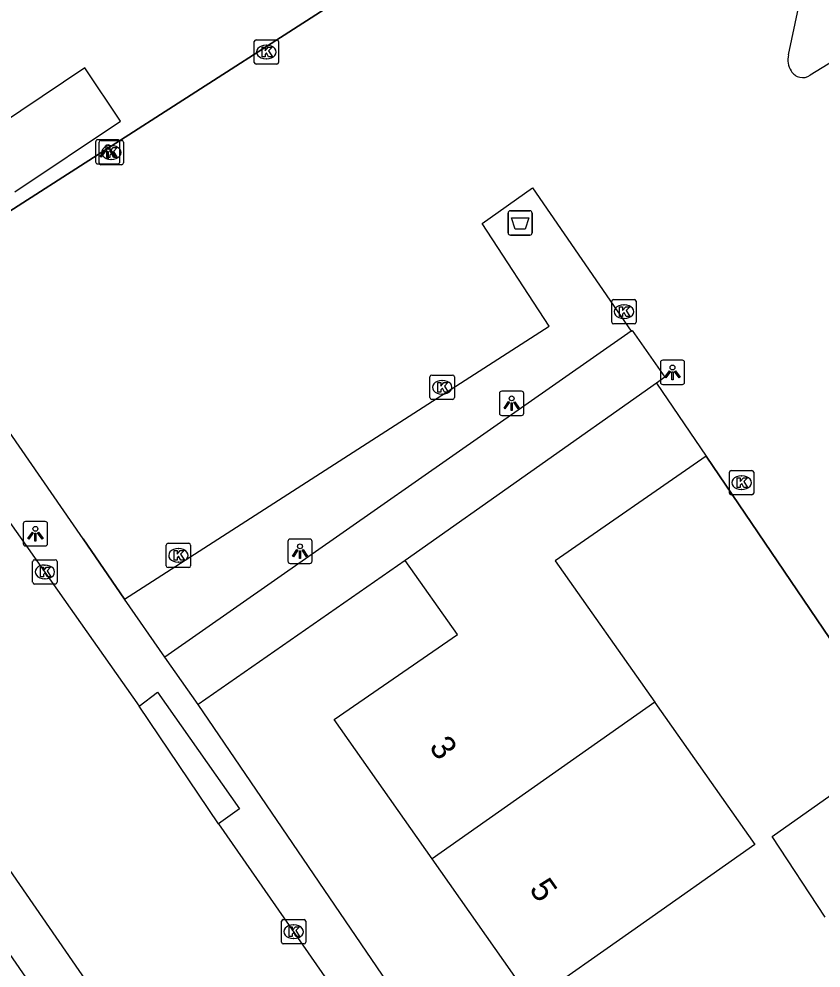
# Model space of a CAD drawing. Extents: x 161845 to 162341, y 381620 to 382158.
# Drawn here: x 162009.89 to 162042.81, y 381891.32 to 381930.27 of the extents above; entities that cross this region are included whole.
import ezdxf

# ---------------------------------------------------------------- set-up
doc = ezdxf.new("R2010")
doc.units = 0
for name, color, linetype in [('IMGEO_Afvalbak', 7, 'Continuous'), ('IMGEO_Kolk', 7, 'Continuous'), ('IMGEO_Lichtpunt', 7, 'Continuous'), ('IMGEO_Muur', 7, 'Continuous'), ('IMGEO_Pand', 7, 'Continuous'), ('IMGEO_Pand_nummerreeks', 7, 'Continuous'), ('IMGEO_Parkeervlak_gesloten', 7, 'Continuous'), ('IMGEO_Rijbaan_lokaal_open', 7, 'Continuous'), ('IMGEO_Voetpad_open', 7, 'Continuous')]:
    doc.layers.add(name, color=color, linetype=linetype)

msp = doc.modelspace()

# ---------------------------------------------------------------- linework, layer by layer
at = {"layer": 'IMGEO_Afvalbak'}
for p, q in [((162029.967, 381921.5), (162029.967, 381922.3)), ((162029.967, 381922.3), (162029.967, 381921.5)), ((162030.067, 381922.4), (162030.857, 381922.4)), ((162030.857, 381922.4), (162030.067, 381922.4)), ((162030.957, 381922.3), (162030.957, 381921.5)), ((162030.957, 381921.5), (162030.957, 381922.3)), ((162030.857, 381921.4), (162030.067, 381921.4)), ((162030.067, 381921.4), (162030.857, 381921.4))]:
    msp.add_line(p, q, dxfattribs=at)
msp.add_lwpolyline([(162030.11, 381922.114), (162030.814, 381922.114), (162030.665, 381921.644), (162030.259, 381921.644), (162030.11, 381922.114)], dxfattribs=at)
for centre, start, end in [((162030.067, 381922.3), 90, 180), ((162030.067, 381922.3), 90, 180), ((162030.857, 381922.3), 0, 90), ((162030.857, 381922.3), 360, 90), ((162030.067, 381921.5), 180, 270), ((162030.067, 381921.5), 180, 270), ((162030.857, 381921.5), 270, 0), ((162030.857, 381921.5), 270, 0)]:
    msp.add_arc(centre, 0.1, start, end, dxfattribs=at)
at = {"layer": 'IMGEO_Kolk'}
for p, q in [((162019.547, 381928.492), (162019.547, 381929.344)), ((162019.622, 381929.418), (162020.474, 381929.418)), ((162020.548, 381929.344), (162020.548, 381928.492)), ((162020.035, 381929.198), (162020.06, 381929.198)), ((162020.058, 381928.638), (162020.033, 381928.638)), ((162020.474, 381928.418), (162019.622, 381928.418)), ((162013.18, 381924.365), (162013.18, 381925.217)), ((162013.255, 381925.291), (162014.107, 381925.291)), ((162013.668, 381925.071), (162013.693, 381925.071)), ((162014.181, 381925.217), (162014.181, 381924.365)), ((162014.107, 381924.291), (162013.255, 381924.291)), ((162013.691, 381924.511), (162013.666, 381924.511)), ((162034.224, 381917.833), (162034.224, 381918.685)), ((162034.299, 381918.759), (162035.151, 381918.759)), ((162034.712, 381918.539), (162034.737, 381918.539)), ((162035.225, 381918.685), (162035.225, 381917.833)), ((162035.151, 381917.759), (162034.299, 381917.759)), ((162034.735, 381917.979), (162034.71, 381917.979)), ((162026.762, 381914.731), (162026.762, 381915.583)), ((162026.837, 381915.657), (162027.689, 381915.657)), ((162027.25, 381915.437), (162027.275, 381915.437)), ((162027.763, 381915.583), (162027.763, 381914.731)), ((162027.689, 381914.657), (162026.837, 381914.657)), ((162027.273, 381914.877), (162027.248, 381914.877)), ((162039.053, 381910.815), (162039.053, 381911.667)), ((162039.128, 381911.741), (162039.98, 381911.741)), ((162039.541, 381911.521), (162039.566, 381911.521)), ((162040.054, 381911.667), (162040.054, 381910.815)), ((162039.98, 381910.741), (162039.128, 381910.741)), ((162039.564, 381910.961), (162039.539, 381910.961)), ((162015.937, 381907.831), (162015.937, 381908.683)), ((162016.012, 381908.757), (162016.864, 381908.757)), ((162016.938, 381908.683), (162016.938, 381907.831)), ((162016.425, 381908.537), (162016.45, 381908.537)), ((162010.454, 381907.153), (162010.454, 381908.005)), ((162010.529, 381908.079), (162011.381, 381908.079)), ((162011.455, 381908.005), (162011.455, 381907.153)), ((162016.448, 381907.977), (162016.423, 381907.977)), ((162010.942, 381907.859), (162010.967, 381907.859)), ((162016.864, 381907.757), (162016.012, 381907.757)), ((162010.965, 381907.299), (162010.94, 381907.299)), ((162011.381, 381907.079), (162010.529, 381907.079)), ((162020.667, 381892.386), (162020.667, 381893.238)), ((162020.742, 381893.312), (162021.594, 381893.312)), ((162021.155, 381893.092), (162021.18, 381893.092)), ((162021.668, 381893.238), (162021.668, 381892.386)), ((162021.594, 381892.312), (162020.742, 381892.312)), ((162021.178, 381892.532), (162021.153, 381892.532))]:
    msp.add_line(p, q, dxfattribs=at)
for points in [[(162019.547, 381928.492), (162019.547, 381929.344)], [(162019.622, 381929.418), (162020.474, 381929.418)], [(162020.548, 381929.344), (162020.548, 381928.492)], [(162019.868, 381929.118), (162019.991, 381929.118), (162019.991, 381928.967), (162020.121, 381929.118), (162020.285, 381929.118), (162020.139, 381928.967), (162020.292, 381928.718), (162020.14, 381928.718), (162020.055, 381928.882), (162019.991, 381928.815), (162019.991, 381928.718), (162019.868, 381928.718), (162019.868, 381929.118)], [(162020.474, 381928.418), (162019.622, 381928.418)], [(162013.18, 381924.365), (162013.18, 381925.217)], [(162013.255, 381925.291), (162014.107, 381925.291)], [(162014.181, 381925.217), (162014.181, 381924.365)], [(162013.501, 381924.991), (162013.624, 381924.991), (162013.624, 381924.84), (162013.754, 381924.991), (162013.918, 381924.991), (162013.772, 381924.84), (162013.925, 381924.591), (162013.773, 381924.591), (162013.688, 381924.755), (162013.624, 381924.688), (162013.624, 381924.591), (162013.501, 381924.591), (162013.501, 381924.991)], [(162014.107, 381924.291), (162013.255, 381924.291)], [(162034.224, 381917.833), (162034.224, 381918.685)], [(162034.299, 381918.759), (162035.151, 381918.759)], [(162034.545, 381918.459), (162034.668, 381918.459), (162034.668, 381918.308), (162034.798, 381918.459), (162034.962, 381918.459), (162034.816, 381918.308), (162034.969, 381918.059), (162034.817, 381918.059), (162034.732, 381918.223), (162034.668, 381918.156), (162034.668, 381918.059), (162034.545, 381918.059), (162034.545, 381918.459)], [(162035.225, 381918.685), (162035.225, 381917.833)], [(162035.151, 381917.759), (162034.299, 381917.759)], [(162026.762, 381914.731), (162026.762, 381915.583)], [(162026.837, 381915.657), (162027.689, 381915.657)], [(162027.083, 381915.357), (162027.206, 381915.357), (162027.206, 381915.206), (162027.336, 381915.357), (162027.5, 381915.357), (162027.354, 381915.206), (162027.507, 381914.957), (162027.355, 381914.957), (162027.27, 381915.121), (162027.206, 381915.054), (162027.206, 381914.957), (162027.083, 381914.957), (162027.083, 381915.357)], [(162027.763, 381915.583), (162027.763, 381914.731)], [(162027.689, 381914.657), (162026.837, 381914.657)], [(162039.053, 381910.815), (162039.053, 381911.667)], [(162039.128, 381911.741), (162039.98, 381911.741)], [(162039.374, 381911.441), (162039.497, 381911.441), (162039.497, 381911.29), (162039.627, 381911.441), (162039.791, 381911.441), (162039.645, 381911.29), (162039.798, 381911.041), (162039.646, 381911.041), (162039.561, 381911.205), (162039.497, 381911.138), (162039.497, 381911.041), (162039.374, 381911.041), (162039.374, 381911.441)], [(162040.054, 381911.667), (162040.054, 381910.815)], [(162039.98, 381910.741), (162039.128, 381910.741)], [(162015.937, 381907.831), (162015.937, 381908.683)], [(162016.012, 381908.757), (162016.864, 381908.757)], [(162016.938, 381908.683), (162016.938, 381907.831)], [(162016.258, 381908.457), (162016.381, 381908.457), (162016.381, 381908.306), (162016.511, 381908.457), (162016.675, 381908.457), (162016.529, 381908.306), (162016.682, 381908.057), (162016.53, 381908.057), (162016.445, 381908.221), (162016.381, 381908.154), (162016.381, 381908.057), (162016.258, 381908.057), (162016.258, 381908.457)], [(162010.454, 381907.153), (162010.454, 381908.005)], [(162010.529, 381908.079), (162011.381, 381908.079)], [(162011.455, 381908.005), (162011.455, 381907.153)], [(162010.775, 381907.779), (162010.898, 381907.779), (162010.898, 381907.628), (162011.028, 381907.779), (162011.192, 381907.779), (162011.046, 381907.628), (162011.199, 381907.379), (162011.047, 381907.379), (162010.962, 381907.543), (162010.898, 381907.476), (162010.898, 381907.379), (162010.775, 381907.379), (162010.775, 381907.779)], [(162016.864, 381907.757), (162016.012, 381907.757)], [(162011.381, 381907.079), (162010.529, 381907.079)], [(162020.667, 381892.386), (162020.667, 381893.238)], [(162020.742, 381893.312), (162021.594, 381893.312)], [(162021.668, 381893.238), (162021.668, 381892.386)], [(162020.988, 381893.012), (162021.111, 381893.012), (162021.111, 381892.861), (162021.241, 381893.012), (162021.405, 381893.012), (162021.259, 381892.861), (162021.412, 381892.612), (162021.26, 381892.612), (162021.175, 381892.776), (162021.111, 381892.709), (162021.111, 381892.612), (162020.988, 381892.612), (162020.988, 381893.012)], [(162021.594, 381892.312), (162020.742, 381892.312)]]:
    msp.add_lwpolyline(points, dxfattribs=at)
for centre, start, end in [((162019.624, 381929.342), 91.552, 178.448), ((162019.624, 381929.342), 91.552, 178.448), ((162020.472, 381929.342), 1.552, 88.448), ((162020.472, 381929.342), 1.552, 88.448), ((162019.624, 381928.494), 181.552, 268.448), ((162019.624, 381928.494), 181.552, 268.448), ((162020.472, 381928.494), 271.552, 358.448), ((162020.472, 381928.494), 271.552, 358.448), ((162013.257, 381925.215), 91.552, 178.448), ((162013.257, 381925.215), 91.552, 178.448), ((162014.105, 381925.215), 1.552, 88.448), ((162014.105, 381925.215), 1.552, 88.448), ((162013.257, 381924.367), 181.552, 268.448), ((162013.257, 381924.367), 181.552, 268.448), ((162014.105, 381924.367), 271.552, 358.448), ((162014.105, 381924.367), 271.552, 358.448), ((162034.301, 381918.683), 91.552, 178.448), ((162034.301, 381918.683), 91.552, 178.448), ((162035.149, 381918.683), 1.552, 88.448), ((162035.149, 381918.683), 1.552, 88.448), ((162034.301, 381917.835), 181.552, 268.448), ((162034.301, 381917.835), 181.552, 268.448), ((162035.149, 381917.835), 271.552, 358.448), ((162035.149, 381917.835), 271.552, 358.448), ((162026.839, 381915.581), 91.552, 178.448), ((162026.839, 381915.581), 91.552, 178.448), ((162027.687, 381915.581), 1.552, 88.448), ((162027.687, 381915.581), 1.552, 88.448), ((162026.839, 381914.733), 181.552, 268.448), ((162026.839, 381914.733), 181.552, 268.448), ((162027.687, 381914.733), 271.552, 358.448), ((162027.687, 381914.733), 271.552, 358.448), ((162039.13, 381911.665), 91.552, 178.448), ((162039.13, 381911.665), 91.552, 178.448), ((162039.978, 381911.665), 1.552, 88.448), ((162039.978, 381911.665), 1.552, 88.448), ((162039.13, 381910.817), 181.552, 268.448), ((162039.13, 381910.817), 181.552, 268.448), ((162039.978, 381910.817), 271.552, 358.448), ((162039.978, 381910.817), 271.552, 358.448), ((162016.014, 381908.681), 91.552, 178.448), ((162016.014, 381908.681), 91.552, 178.448), ((162016.862, 381908.681), 1.552, 88.448), ((162016.862, 381908.681), 1.552, 88.448), ((162010.531, 381908.003), 91.552, 178.448), ((162010.531, 381908.003), 91.552, 178.448), ((162011.379, 381908.003), 1.552, 88.448), ((162011.379, 381908.003), 1.552, 88.448), ((162016.014, 381907.833), 181.552, 268.448), ((162016.014, 381907.833), 181.552, 268.448), ((162016.862, 381907.833), 271.552, 358.448), ((162016.862, 381907.833), 271.552, 358.448), ((162010.531, 381907.155), 181.552, 268.448), ((162010.531, 381907.155), 181.552, 268.448), ((162011.379, 381907.155), 271.552, 358.448), ((162011.379, 381907.155), 271.552, 358.448), ((162020.744, 381893.236), 91.552, 178.448), ((162020.744, 381893.236), 91.552, 178.448), ((162021.592, 381893.236), 1.552, 88.448), ((162021.592, 381893.236), 1.552, 88.448), ((162020.744, 381892.388), 181.552, 268.448), ((162020.744, 381892.388), 181.552, 268.448), ((162021.592, 381892.388), 271.552, 358.448), ((162021.592, 381892.388), 271.552, 358.448)]:
    msp.add_arc(centre, 0.0765, start, end, dxfattribs=at)
for centre, major_axis, ratio, start_param, end_param in [((162020.034, 381928.918), (-0.387, 0.002), 0.722429, 4.712389, 7.853982), ((162020.059, 381928.918), (-0.39, 0.002), 0.717154, 1.570796, 4.712389), ((162013.667, 381924.791), (-0.387, 0.002), 0.722429, 4.712389, 7.853982), ((162013.692, 381924.791), (-0.39, 0.002), 0.717154, 1.570796, 4.712389), ((162034.711, 381918.259), (-0.387, 0.002), 0.722429, 4.712389, 7.853982), ((162034.736, 381918.259), (-0.39, 0.002), 0.717154, 1.570796, 4.712389), ((162027.249, 381915.157), (-0.387, 0.002), 0.722429, 4.712389, 7.853982), ((162027.274, 381915.157), (-0.39, 0.002), 0.717154, 1.570796, 4.712389), ((162039.54, 381911.241), (-0.387, 0.002), 0.722429, 4.712389, 7.853982), ((162039.565, 381911.241), (-0.39, 0.002), 0.717154, 1.570796, 4.712389), ((162016.424, 381908.257), (-0.387, 0.002), 0.722429, 4.712389, 7.853982), ((162016.449, 381908.257), (-0.39, 0.002), 0.717154, 1.570796, 4.712389), ((162010.941, 381907.579), (-0.387, 0.002), 0.722429, 4.712389, 7.853982), ((162010.966, 381907.579), (-0.39, 0.002), 0.717154, 1.570796, 4.712389), ((162021.154, 381892.812), (-0.387, 0.002), 0.722429, 4.712389, 7.853982), ((162021.179, 381892.812), (-0.39, 0.002), 0.717154, 1.570796, 4.712389)]:
    msp.add_ellipse(centre, major_axis=major_axis, ratio=ratio, start_param=start_param, end_param=end_param, dxfattribs=at)
at = {"layer": 'IMGEO_Lichtpunt'}
for p, q in [((162013.037, 381925.223), (162013.037, 381924.416)), ((162013.037, 381925.223), (162013.037, 381924.416)), ((162013.939, 381925.318), (162013.131, 381925.318)), ((162013.939, 381925.318), (162013.131, 381925.318)), ((162014.033, 381924.416), (162014.033, 381925.223)), ((162014.033, 381924.416), (162014.033, 381925.223)), ((162013.131, 381924.322), (162013.939, 381924.322)), ((162013.131, 381924.322), (162013.939, 381924.322)), ((162036.22, 381916.172), (162036.22, 381915.365)), ((162036.22, 381916.172), (162036.22, 381915.365)), ((162037.122, 381916.267), (162036.314, 381916.267)), ((162037.122, 381916.267), (162036.314, 381916.267)), ((162037.216, 381915.365), (162037.216, 381916.172)), ((162037.216, 381915.365), (162037.216, 381916.172)), ((162029.615, 381914.903), (162029.615, 381914.096)), ((162029.615, 381914.903), (162029.615, 381914.096)), ((162030.517, 381914.998), (162029.709, 381914.998)), ((162030.517, 381914.998), (162029.709, 381914.998)), ((162030.611, 381914.096), (162030.611, 381914.903)), ((162030.611, 381914.096), (162030.611, 381914.903)), ((162036.314, 381915.271), (162037.122, 381915.271)), ((162036.314, 381915.271), (162037.122, 381915.271)), ((162029.709, 381914.002), (162030.517, 381914.002)), ((162029.709, 381914.002), (162030.517, 381914.002)), ((162010.068, 381909.55), (162010.068, 381908.743)), ((162010.068, 381909.55), (162010.068, 381908.743)), ((162010.97, 381909.645), (162010.162, 381909.645)), ((162010.97, 381909.645), (162010.162, 381909.645)), ((162011.064, 381908.743), (162011.064, 381909.55)), ((162011.064, 381908.743), (162011.064, 381909.55)), ((162020.929, 381908.83), (162020.929, 381908.023)), ((162020.929, 381908.83), (162020.929, 381908.023)), ((162021.831, 381908.925), (162021.023, 381908.925)), ((162021.831, 381908.925), (162021.023, 381908.925)), ((162021.925, 381908.023), (162021.925, 381908.83)), ((162021.925, 381908.023), (162021.925, 381908.83)), ((162010.162, 381908.649), (162010.97, 381908.649)), ((162010.162, 381908.649), (162010.97, 381908.649)), ((162021.023, 381907.929), (162021.831, 381907.929)), ((162021.023, 381907.929), (162021.831, 381907.929))]:
    msp.add_line(p, q, dxfattribs=at)
for points in [[(162013.411, 381924.887), (162013.45, 381924.859), (162013.262, 381924.597), (162013.224, 381924.624), (162013.411, 381924.887)], [(162013.513, 381924.839), (162013.56, 381924.839), (162013.56, 381924.517), (162013.513, 381924.517), (162013.513, 381924.839)], [(162013.623, 381924.859), (162013.661, 381924.886), (162013.848, 381924.624), (162013.809, 381924.596), (162013.623, 381924.859)], [(162036.594, 381915.836), (162036.633, 381915.808), (162036.445, 381915.546), (162036.407, 381915.573), (162036.594, 381915.836)], [(162036.696, 381915.788), (162036.743, 381915.788), (162036.743, 381915.466), (162036.696, 381915.466), (162036.696, 381915.788)], [(162036.806, 381915.808), (162036.844, 381915.835), (162037.031, 381915.573), (162036.992, 381915.545), (162036.806, 381915.808)], [(162029.989, 381914.567), (162030.028, 381914.539), (162029.84, 381914.277), (162029.802, 381914.304), (162029.989, 381914.567)], [(162030.091, 381914.519), (162030.138, 381914.519), (162030.138, 381914.197), (162030.091, 381914.197), (162030.091, 381914.519)], [(162030.201, 381914.539), (162030.239, 381914.566), (162030.426, 381914.304), (162030.387, 381914.276), (162030.201, 381914.539)], [(162010.442, 381909.214), (162010.481, 381909.186), (162010.293, 381908.924), (162010.255, 381908.951), (162010.442, 381909.214)], [(162010.544, 381909.166), (162010.591, 381909.166), (162010.591, 381908.844), (162010.544, 381908.844), (162010.544, 381909.166)], [(162010.654, 381909.186), (162010.692, 381909.213), (162010.879, 381908.951), (162010.84, 381908.923), (162010.654, 381909.186)], [(162021.303, 381908.494), (162021.342, 381908.466), (162021.154, 381908.204), (162021.116, 381908.231), (162021.303, 381908.494)], [(162021.405, 381908.446), (162021.452, 381908.446), (162021.452, 381908.124), (162021.405, 381908.124), (162021.405, 381908.446)], [(162021.515, 381908.466), (162021.553, 381908.493), (162021.74, 381908.231), (162021.701, 381908.203), (162021.515, 381908.466)]]:
    msp.add_lwpolyline(points, dxfattribs=at)
for centre in [(162013.536, 381925.021), (162036.719, 381915.97), (162030.114, 381914.701), (162010.567, 381909.348), (162021.428, 381908.628)]:
    msp.add_circle(centre, 0.0994, dxfattribs=at)
for centre, start, end in [((162013.131, 381925.223), 90, 180), ((162013.131, 381925.223), 90, 180), ((162013.939, 381925.223), 0, 90), ((162013.939, 381925.223), 0, 90), ((162013.131, 381924.416), 180, 270), ((162013.131, 381924.416), 180, 270), ((162013.939, 381924.416), 270, 0), ((162013.939, 381924.416), 270, 360), ((162036.314, 381916.172), 90, 180), ((162036.314, 381916.172), 90, 180), ((162037.122, 381916.172), 0, 90), ((162037.122, 381916.172), 0, 90), ((162036.314, 381915.365), 180, 270), ((162036.314, 381915.365), 180, 270), ((162037.122, 381915.365), 270, 0), ((162037.122, 381915.365), 270, 360), ((162029.709, 381914.903), 90, 180), ((162029.709, 381914.903), 90, 180), ((162030.517, 381914.903), 0, 90), ((162030.517, 381914.903), 0, 90), ((162029.709, 381914.096), 180, 270), ((162029.709, 381914.096), 180, 270), ((162030.517, 381914.096), 270, 0), ((162030.517, 381914.096), 270, 360), ((162010.162, 381909.55), 90, 180), ((162010.162, 381909.55), 90, 180), ((162010.97, 381909.55), 0, 90), ((162010.97, 381909.55), 0, 90), ((162010.162, 381908.743), 180, 270), ((162010.162, 381908.743), 180, 270), ((162010.97, 381908.743), 270, 0), ((162010.97, 381908.743), 270, 360), ((162021.023, 381908.83), 90, 180), ((162021.023, 381908.83), 90, 180), ((162021.831, 381908.83), 0, 90), ((162021.831, 381908.83), 0, 90), ((162021.023, 381908.023), 180, 270), ((162021.023, 381908.023), 180, 270), ((162021.831, 381908.023), 270, 0), ((162021.831, 381908.023), 270, 360)]:
    msp.add_arc(centre, 0.0946, start, end, dxfattribs=at)
at = {"layer": 'IMGEO_Muur'}
for points in [[(162029.183, 381935.015), (162005.116, 381919.57)], [(162038.103, 381912.325), (162044.506, 381902.893)], [(162012.533, 381908.931), (162014.227, 381906.459)]]:
    msp.add_lwpolyline(points, dxfattribs=at)
at = {"layer": 'IMGEO_Pand'}
for points in [[(162009.717, 381923.179), (162014.054, 381926.081), (162012.595, 381928.262), (162008.206, 381925.326)], [(162035.022, 381917.456), (162015.873, 381904.079)], [(162035.022, 381917.456), (162035.065, 381917.486), (162036.407, 381915.571), (162036.064, 381915.328)], [(162036.064, 381915.328), (162025.75, 381908.052)], [(162036.064, 381915.328), (162038.103, 381912.325)], [(162038.103, 381912.325), (162031.902, 381908.035), (162035.987, 381902.228)], [(162025.75, 381908.052), (162017.248, 381902.136)], [(162026.851, 381895.799), (162022.827, 381901.517), (162027.887, 381905.012), (162025.75, 381908.052)], [(162017.248, 381902.136), (162015.873, 381904.079)], [(162035.987, 381902.228), (162035.997, 381902.214), (162040.096, 381896.387), (162035.051, 381892.839), (162030.962, 381889.96), (162026.851, 381895.799)], [(162035.987, 381902.228), (162026.851, 381895.799)], [(162042.987, 381893.41), (162040.807, 381896.726), (162046.118, 381900.465), (162048.376, 381897.029)]]:
    msp.add_lwpolyline(points, dxfattribs=at)
at = {"layer": 'IMGEO_Parkeervlak_gesloten'}
for points in [[(162005.116, 381919.57), (162029.183, 381935.015), (162031.394, 381936.463)], [(162058.126, 381911.732), (162044.506, 381902.893), (162038.103, 381912.325)]]:
    msp.add_lwpolyline(points, dxfattribs=at)
at = {"layer": 'IMGEO_Rijbaan_lokaal_open'}
for points in [[(161992.276, 381934.334), (162005.472, 381915.32), (162010.266, 381908.536), (162014.832, 381902.075)], [(162018.077, 381897.245), (162014.832, 381902.075)], [(162016.258, 381885.569), (162005.739, 381900.791)], [(162018.077, 381897.245), (162023.67, 381889.204), (162024.48, 381887.904)]]:
    msp.add_lwpolyline(points, dxfattribs=at)
at = {"layer": 'IMGEO_Voetpad_open'}
for points in [[(162041.474, 381928.798), (162042.402, 381933.125)], [(162058.126, 381911.732), (162056.285, 381914.527), (162052.024, 381911.928), (162049.187, 381916.36), (162053.475, 381918.951), (162046.135, 381930.265), (162042.368, 381927.965)], [(162014.227, 381906.459), (162031.65, 381917.659), (162028.903, 381921.875), (162030.967, 381923.349), (162035.022, 381917.456)], [(162014.227, 381906.459), (162012.533, 381908.931), (162009.099, 381913.886), (162005.116, 381919.57)], [(162015.873, 381904.079), (162014.227, 381906.459)], [(162014.832, 381902.075), (162015.58, 381902.649), (162018.946, 381897.86), (162018.077, 381897.245)], [(162026.737, 381888.194), (162017.248, 381902.136)], [(161993.909, 381784.124), (162000, 381811.259), (162006.057, 381838.422), (162012.585, 381866.816), (162015.506, 381878.919), (162015.663, 381880.219), (162015.619, 381881.528), (162015.122, 381883.128), (162013.985, 381885.418), (162004.242, 381899.525), (162004.132, 381899.684)]]:
    msp.add_lwpolyline(points, dxfattribs=at)
for centre, radius, start, end in [((162042.329, 381928.608), 0.876, 167.484, 212.0925), ((162042.058, 381928.405), 0.539, 209.1353, 305.1864)]:
    msp.add_arc(centre, radius, start, end, dxfattribs=at)

# ---------------------------------------------------------------- texts
at = {"layer": 'IMGEO_Pand_nummerreeks'}
for s, p in [('3', (162026.699, 381900.393)), ('5', (162030.809, 381894.555))]:
    msp.add_text(s, height=1, rotation=305.1435, dxfattribs=at).set_placement(p)

doc.saveas('drawing.dxf')
